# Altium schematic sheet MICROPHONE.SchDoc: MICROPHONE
size A4; CompanyName: Arduino srl; DrawnBy: Silvio Navaretti; DocumentNumber: ASX00039; SheetNumber: 8; SheetTotal: 8; RevAuthor: Silvio Navaretti
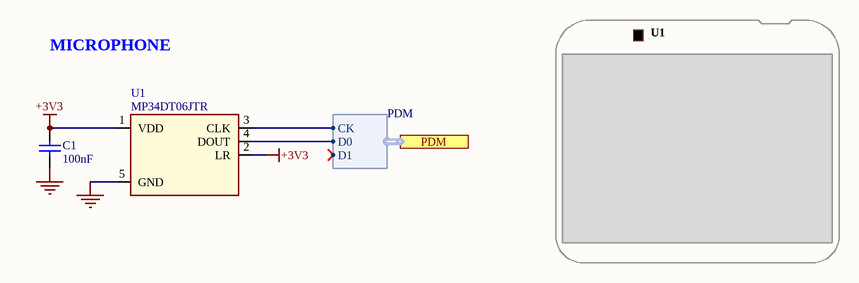
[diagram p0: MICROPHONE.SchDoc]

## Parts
C1  value 100nF  [CAP-0603]  (hidden comment: C0603C104K5RAC3190)
U1  MP34DT06JTR  [HCLGA]

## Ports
PDM (harness PDM)

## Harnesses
PDM: CK, D0, D1

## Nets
+3V3: C1.2 U1.1(VDD) U1.2(LR)
GND: C1.1 U1.5(GND)
NetU1_3: U1.3(CLK) ; port PDM.CK
NetU1_4: U1.4(DOUT) ; port PDM.D0

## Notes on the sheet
- MICROPHONE
- U1

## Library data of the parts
C1 = C0043-A.11: CAP CHIP 0603 100nF 50V X7R 10%; Manufacturer: KEMET; Code Arduino: 0015
U1 = U0074-A.4: SENS MEMS AUDIO OMNIDIRECTIONAL; Manufacturer: STMicroelectronics; Device Type: SENSOR; Code Arduino: A5470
